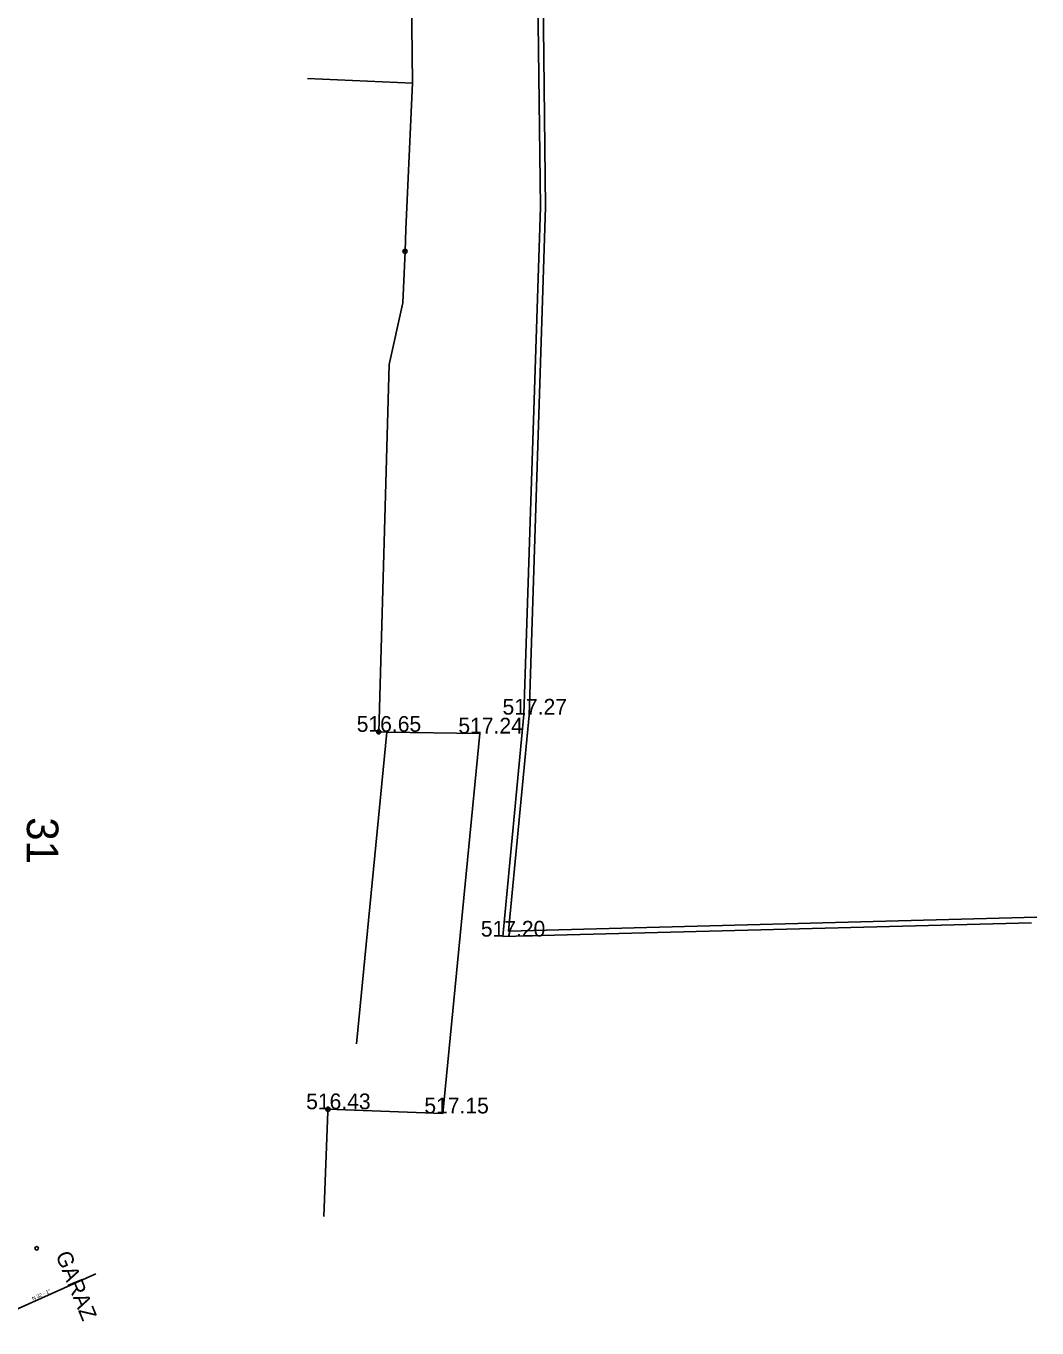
# Model space of a CAD drawing. Extents: x -669642 to -669119, y -1131006 to -1130466.
# Drawn here: x -669366.1 to -669318, y -1130941 to -1130879 of the extents above; entities that cross this region are included whole.
import ezdxf

# ---------------------------------------------------------------- set-up
doc = ezdxf.new("R2010")
doc.units = 0
for name, color, linetype in [('G_Bod_tecka', 7, 'Continuous'), ('G_Bod_vyska', 7, 'Continuous'), ('G_Budovy-znacky', 7, 'Continuous'), ('G_Cisla_orientacni', 7, 'Continuous'), ('G_Ploty', 7, 'Continuous'), ('G_Popisy_objektu', 7, 'Continuous'), ('G_Site-Sloupy', 7, 'Continuous'), ('G_Z_VODA_podz_kotovane', 7, 'Continuous'), ('Vrstva 25', 7, 'Continuous'), ('Vrstva 4', 7, 'Continuous')]:
    doc.layers.add(name, color=color, linetype=linetype)

msp = doc.modelspace()

# ---------------------------------------------------------------- linework, layer by layer
at = {"layer": 'G_Bod_tecka'}
for p, q in [((-669342.4, -1130911.77), (-669342.4, -1130911.77)), ((-669349.31, -1130912.59), (-669349.31, -1130912.59)), ((-669344.5, -1130912.67), (-669344.5, -1130912.67)), ((-669343.41, -1130922.34), (-669343.41, -1130922.34)), ((-669351.73, -1130930.56), (-669351.73, -1130930.56)), ((-669346.26, -1130930.76), (-669346.26, -1130930.76))]:
    msp.add_line(p, q, dxfattribs=at)
at = {"layer": 'G_Budovy-znacky'}
msp.add_circle((-669365.59, -1130937.181), 0.0875, dxfattribs=at)
at = {"layer": 'G_Ploty'}
for p, q in [((-669342.04, -1130851.69), (-669341.62, -1130887.61)), ((-669341.37, -1130887.61), (-669341.79, -1130851.69)), ((-669347.8, -1130872.92), (-669347.71, -1130881.7)), ((-669347.71, -1130881.7), (-669352.7, -1130881.48)), ((-669347.71, -1130881.7), (-669348.02, -1130888.66)), ((-669341.62, -1130887.61), (-669342.4, -1130911.77)), ((-669342.15, -1130911.79), (-669341.37, -1130887.61)), ((-669348.02, -1130888.66), (-669348.06, -1130889.71)), ((-669348.06, -1130889.71), (-669348.16, -1130892.16)), ((-669342.4, -1130911.77), (-669343.41, -1130922.34)), ((-669343.13, -1130922.08), (-669342.15, -1130911.79)), ((-669348.92, -1130912.6), (-669350.37, -1130927.44)), ((-669344.5, -1130912.67), (-669346.26, -1130930.76)), ((-669317.99, -1130921.42), (-669343.13, -1130922.08)), ((-669343.41, -1130922.34), (-669318.25, -1130921.68)), ((-669351.73, -1130930.67), (-669351.92, -1130935.66)), ((-669346.26, -1130930.76), (-669351.73, -1130930.56))]:
    msp.add_line(p, q, dxfattribs=at)
for points in [[(-669348.16, -1130892.16), (-669348.81, -1130895.1), (-669349.31, -1130912.59)], [(-669349.31, -1130912.59), (-669348.92, -1130912.6), (-669344.5, -1130912.67)]]:
    msp.add_lwpolyline(points, dxfattribs=at)
at = {"layer": 'G_Site-Sloupy'}
for centre, radius in [((-669348.06, -1130889.71), 0.1), ((-669348.06, -1130889.71), 0.0348), ((-669349.31, -1130912.59), 0.1), ((-669349.31, -1130912.59), 0.0348), ((-669351.73, -1130930.56), 0.1), ((-669351.73, -1130930.56), 0.0348)]:
    msp.add_circle(centre, radius, dxfattribs=at)
at = {"layer": 'G_Z_VODA_podz_kotovane'}
msp.add_line((-669368.55, -1130940.97), (-669362.78, -1130938.4), dxfattribs=at)
at = {"layer": 'Vrstva 25'}
msp.add_line((-669368.55, -1130940.973), (-669362.783, -1130938.399), dxfattribs=at)

# ---------------------------------------------------------------- texts
at = {"layer": 'G_Bod_vyska'}
for s, p in [('517.27', (-669343.422, -1130911.77)), ('516.65', (-669350.36, -1130912.59)), ('517.24', (-669345.522, -1130912.67)), ('517.20', (-669344.454, -1130922.34)), ('516.43', (-669352.766, -1130930.56)), ('517.15', (-669347.141, -1130930.76))]:
    msp.add_text(s, height=0.75, dxfattribs=at).set_placement(p)
at = {"layer": 'G_Cisla_orientacni'}
msp.add_text('31', height=1.5, rotation=269.51638, dxfattribs=at).set_placement((-669366.052, -1130916.649))
at = {"layer": 'G_Popisy_objektu'}
msp.add_text('GARAZ', height=0.75, rotation=292.21345, dxfattribs=at).set_placement((-669364.704, -1130937.495))
at = {"layer": 'Vrstva 4'}
msp.add_text('N 32 - 1"', height=0.1755, rotation=24.05018, dxfattribs=at).set_placement((-669365.771, -1130939.665))

doc.saveas('drawing.dxf')
